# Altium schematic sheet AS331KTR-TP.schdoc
size 127 x 101 mm
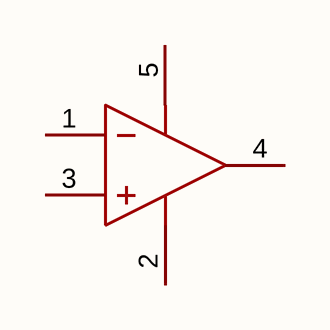
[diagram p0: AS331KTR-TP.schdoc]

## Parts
U?  as331ktr-tp  [SOT-23-5_L3.0-W1.7-P0.95-LS2.8-BR]  (value not drawn)

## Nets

Not connected (* = marked no-connect by the designer): U? 1(-IN) 2(V-) 3(+IN) 4(OUT) 5(V+)

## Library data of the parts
U? = as331ktr-tp: 比较器数:单路;输入失调电压(Vos):2mV;输入偏置电流(Ib):25nA;; Manufacturer: TECH PUBLIC(台舟); AddInBom: yes; ModelId: 0a2a1b8f50944f73965918ad6e5fe167; ModelName: SOT-23-5_L2.9-W1.6-H1.1-LS2.8-P0.95; ModelTransform: 114.173,109.636,0,180,0,0,0,0,0; Number of Channels: 单路; Vos - Input Offset Voltage: 2mV; Ib - Input Bias Current: 25nA; Propagation Delay Time: 300ns; Quiescent Current: 400uA; Maximum Power Supply Range (Vdd-Vss): 36V; Single Supply: 2V~36V; Dual Supply: 1V~18V；-18V~-1V; Input Offset Current(Ios): 50nA; Response Time (tr): 1.3us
